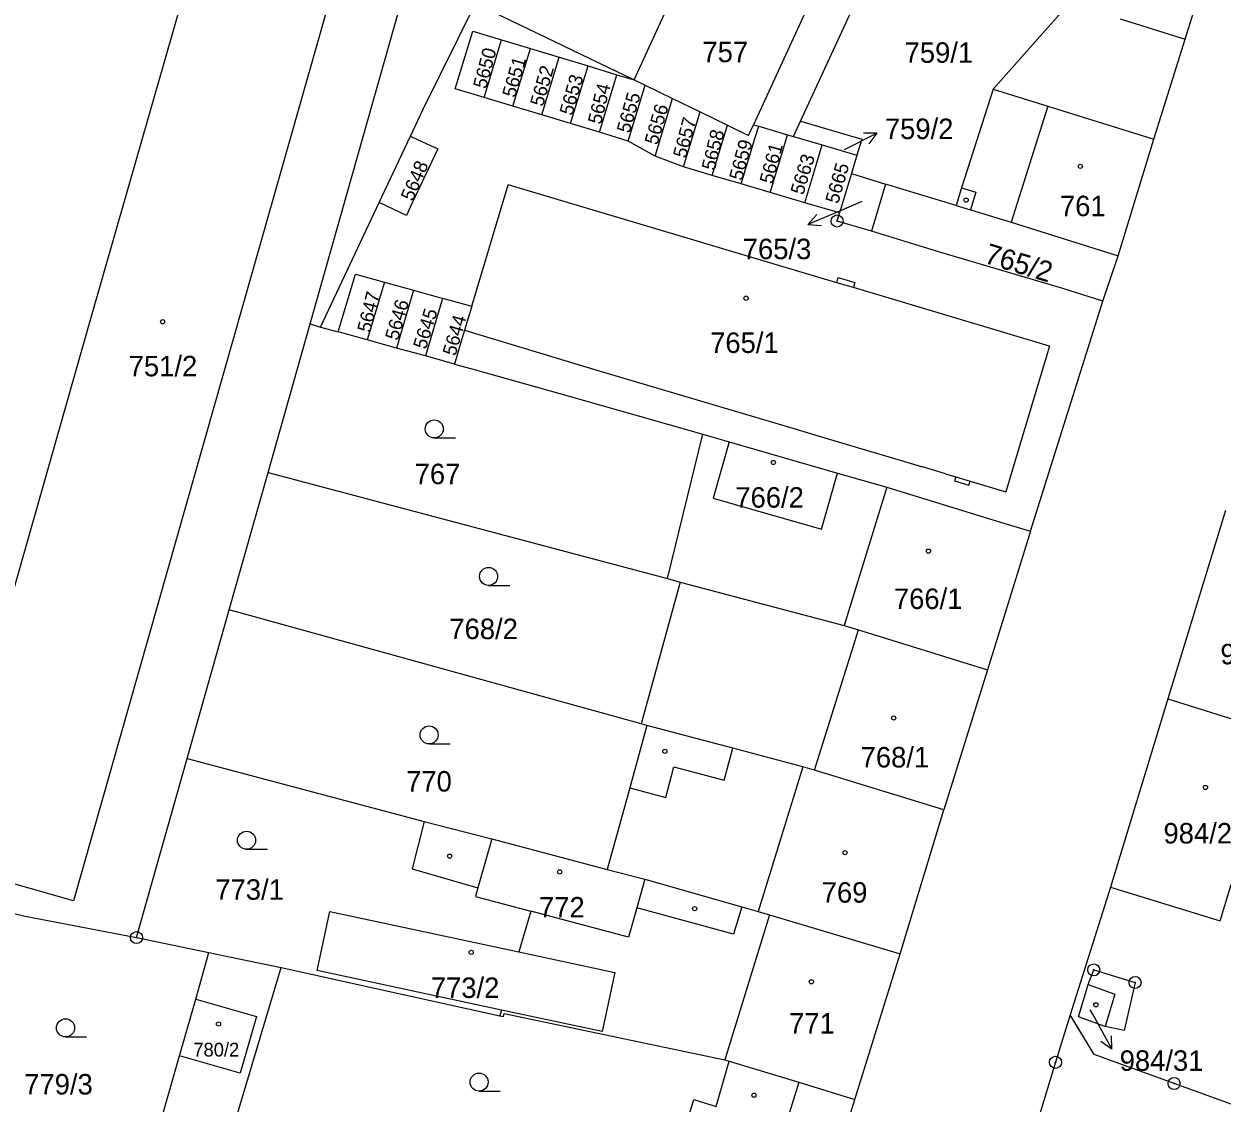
# Model space of a CAD drawing. Extents: x -733394 to -722299, y -1082822 to -1075049.
# Drawn here: x -727904 to -727804.6, y -1079351.3 to -1079261.8 of the extents above; entities that cross this region are included whole.
import ezdxf

# ---------------------------------------------------------------- set-up
doc = ezdxf.new("R2010")
doc.units = 0
for name, color, linetype in [('Hranice parcel', 7, 'Continuous'), ('Parcelní čísla', 7, 'Continuous'), ('Pop  PČ popisy', 7, 'Continuous'), ('Vnitřní kresba', 7, 'Continuous'), ('Značky bodu BP', 7, 'Continuous'), ('Značky budov', 7, 'Continuous'), ('Značky kultur', 7, 'Continuous')]:
    doc.layers.add(name, color=color, linetype=linetype)

msp = doc.modelspace()

# ---------------------------------------------------------------- linework, layer by layer
at = {"layer": 'Hranice parcel'}
for p, q in [((-727853.37, -1079266.43), (-727847.88, -1079254.4)), ((-727866.53, -1079260.08), (-727853.37, -1079266.43)), ((-727817.72, -1079260.59), (-727823.56, -1079267.19)), ((-727865.82, -1079267.89), (-727864.37, -1079263.1)), ((-727864.37, -1079263.1), (-727861.98, -1079263.82)), ((-727863.42, -1079268.61), (-727861.98, -1079263.82)), ((-727861.98, -1079263.82), (-727859.59, -1079264.55)), ((-727861.03, -1079269.34), (-727859.59, -1079264.55)), ((-727859.59, -1079264.55), (-727857.19, -1079265.27)), ((-727858.64, -1079270.06), (-727857.19, -1079265.27)), ((-727857.19, -1079265.27), (-727854.8, -1079266)), ((-727856.25, -1079270.78), (-727854.8, -1079266)), ((-727854.8, -1079266), (-727853.37, -1079266.43)), ((-727853.37, -1079266.43), (-727852.45, -1079266.87)), ((-727853.85, -1079271.51), (-727852.45, -1079266.87)), ((-727852.45, -1079266.87), (-727850.17, -1079267.98)), ((-727863.42, -1079268.61), (-727865.82, -1079267.89)), ((-727851.62, -1079272.75), (-727850.17, -1079267.98)), ((-727850.17, -1079267.98), (-727847.9, -1079269.08)), ((-727861.03, -1079269.34), (-727863.42, -1079268.61)), ((-727858.64, -1079270.06), (-727861.03, -1079269.34)), ((-727849.27, -1079273.64), (-727847.9, -1079269.08)), ((-727847.9, -1079269.08), (-727845.62, -1079270.18)), ((-727856.25, -1079270.78), (-727858.64, -1079270.06)), ((-727846.88, -1079274.35), (-727845.62, -1079270.18)), ((-727843.46, -1079270.15), (-727843.03, -1079270.28)), ((-727843.03, -1079270.28), (-727840.64, -1079270.98)), ((-727840.14, -1079271.13), (-727839.56, -1079269.86)), ((-727874.53, -1079276.61), (-727871.93, -1079271.09)), ((-727853.85, -1079271.51), (-727856.25, -1079270.78)), ((-727851.62, -1079272.75), (-727853.85, -1079271.51)), ((-727840.64, -1079270.98), (-727840.14, -1079271.13)), ((-727840.14, -1079271.13), (-727837.76, -1079271.83)), ((-727813.21, -1079281.03), (-727810.23, -1079271.36)), ((-727837.76, -1079271.83), (-727834.88, -1079272.68)), ((-727849.27, -1079273.64), (-727851.62, -1079272.75)), ((-727834.88, -1079272.68), (-727835.34, -1079274.2)), ((-727846.88, -1079274.35), (-727849.27, -1079273.64)), ((-727844.48, -1079275.06), (-727846.88, -1079274.35)), ((-727835.34, -1079274.2), (-727836.33, -1079277.47)), ((-727835.34, -1079274.2), (-727832.5, -1079275.08)), ((-727842.08, -1079275.77), (-727844.48, -1079275.06)), ((-727832.5, -1079275.08), (-727833.66, -1079278.98)), ((-727826.65, -1079276.85), (-727832.5, -1079275.08)), ((-727839.2, -1079276.62), (-727842.08, -1079275.77)), ((-727879.39, -1079286.94), (-727874.53, -1079276.61)), ((-727836.33, -1079277.47), (-727839.2, -1079276.62)), ((-727814.46, -1079284.79), (-727813.21, -1079281.03)), ((-727874.08, -1079283.22), (-727875.51, -1079288.01)), ((-727874.08, -1079283.22), (-727871.67, -1079283.89)), ((-727871.67, -1079283.89), (-727873.1, -1079288.68)), ((-727820.47, -1079303.88), (-727814.46, -1079284.79)), ((-727883.74, -1079299), (-727880.25, -1079286.67)), ((-727880.25, -1079286.67), (-727879.39, -1079286.94)), ((-727879.39, -1079286.94), (-727877.92, -1079287.35)), ((-727875.51, -1079288.01), (-727877.92, -1079287.35)), ((-727873.1, -1079288.68), (-727875.51, -1079288.01)), ((-727870.69, -1079289.34), (-727873.1, -1079288.68)), ((-727868.28, -1079290.01), (-727870.69, -1079289.34)), ((-727850.61, -1079307.8), (-727847.67, -1079295.84)), ((-727847.67, -1079295.84), (-727845.48, -1079296.47)), ((-727845.48, -1079296.47), (-727836.49, -1079299.06)), ((-727886.96, -1079310.4), (-727883.74, -1079299)), ((-727883.74, -1079299), (-727850.61, -1079307.8)), ((-727804.29, -1079302.16), (-727809.07, -1079317.79)), ((-727820.47, -1079303.88), (-727824.04, -1079315.38)), ((-727849.56, -1079308.1), (-727852.77, -1079319.88)), ((-727850.61, -1079307.8), (-727849.56, -1079308.1)), ((-727849.56, -1079308.1), (-727835.95, -1079311.7)), ((-727890.46, -1079322.76), (-727886.96, -1079310.4)), ((-727852.77, -1079319.88), (-727886.96, -1079310.4)), ((-727824.04, -1079315.38), (-727827.66, -1079327.02)), ((-727809.07, -1079317.79), (-727813.84, -1079333.42)), ((-727809.07, -1079317.79), (-727800.01, -1079320.63)), ((-727852.32, -1079320), (-727852.77, -1079319.88)), ((-727894.66, -1079337.61), (-727890.46, -1079322.76)), ((-727890.46, -1079322.76), (-727870.8, -1079327.98)), ((-727831.29, -1079338.96), (-727827.66, -1079327.02)), ((-727813.84, -1079333.42), (-727817.18, -1079344.01)), ((-727861.95, -1079335.43), (-727862.94, -1079338.8)), ((-727894.66, -1079337.61), (-727888.65, -1079338.84)), ((-727835.04, -1079351.06), (-727831.29, -1079338.96)), ((-727882.65, -1079340.09), (-727864.5, -1079344.11)), ((-727864.36, -1079343.62), (-727864.5, -1079344.11)), ((-727845.48, -1079347.87), (-727839.71, -1079349.61)), ((-727839.71, -1079349.61), (-727835.04, -1079351.06)), ((-727840.81, -1079369.25), (-727835.04, -1079351.06))]:
    msp.add_line(p, q, dxfattribs=at)
for points in [[(-727875.06, -1079247.14), (-727899.89, -1079334.57), (-727911.3, -1079331.32), (-727898.45, -1079286.22), (-727886.35, -1079243.97)], [(-727880.25, -1079286.67), (-727868.91, -1079246.6), (-727874.92, -1079243.71)], [(-727810.23, -1079271.36), (-727807.63, -1079263.04), (-727804.03, -1079251.5), (-727804.69, -1079249.96)], [(-727847.76, -1079254.13), (-727838.1, -1079258.46), (-727843.46, -1079270.15)], [(-727839.56, -1079269.86), (-727834.94, -1079259.88), (-727832.41, -1079254.24)], [(-727871.93, -1079271.09), (-727870.9, -1079268.9), (-727866.53, -1079260.08)], [(-727865.82, -1079267.89), (-727868.21, -1079267.16), (-727866.76, -1079262.38), (-727864.37, -1079263.1)], [(-727823.56, -1079267.19), (-727826.2, -1079275.38), (-727826.65, -1079276.85)], [(-727823.56, -1079267.19), (-727819.05, -1079268.6), (-727810.23, -1079271.36)], [(-727845.62, -1079270.18), (-727843.87, -1079271.03), (-727843.46, -1079270.15)], [(-727844.48, -1079275.06), (-727843.34, -1079271.29), (-727843.03, -1079270.28)], [(-727839.56, -1079269.86), (-727834.48, -1079271.36), (-727834.88, -1079272.68)], [(-727871.93, -1079271.09), (-727871.23, -1079271.42), (-727869.67, -1079272.16), (-727871.95, -1079276.99), (-727872.27, -1079277.68), (-727874.53, -1079276.61)], [(-727842.08, -1079275.77), (-727841.06, -1079272.39), (-727840.64, -1079270.98)], [(-727839.2, -1079276.62), (-727838.21, -1079273.32), (-727837.76, -1079271.83)], [(-727833.66, -1079278.98), (-727836.53, -1079278.14), (-727836.33, -1079277.47)], [(-727826.65, -1079276.85), (-727825.46, -1079277.22), (-727822.08, -1079278.25), (-727813.21, -1079281.03)], [(-727814.46, -1079284.79), (-727817.8, -1079283.75), (-727827.92, -1079280.74), (-727833.66, -1079278.98)], [(-727877.92, -1079287.35), (-727876.49, -1079282.56), (-727874.08, -1079283.22)], [(-727871.67, -1079283.89), (-727869.52, -1079284.48), (-727869.26, -1079284.55)], [(-727869.26, -1079284.55), (-727869.34, -1079284.84), (-727870.69, -1079289.34)], [(-727869.26, -1079284.55), (-727866.84, -1079285.22), (-727867.44, -1079287.21), (-727867.71, -1079288.12), (-727868.28, -1079290.01)], [(-727868.28, -1079290.01), (-727866.54, -1079290.49), (-727858.75, -1079292.68), (-727847.67, -1079295.84)], [(-727845.48, -1079296.47), (-727846.82, -1079301.13), (-727837.83, -1079303.72), (-727836.49, -1079299.06)], [(-727836.49, -1079299.06), (-727832.41, -1079300.24), (-727823.25, -1079303.04), (-727820.47, -1079303.88)], [(-727835.95, -1079311.7), (-727834.76, -1079312.07), (-727824.04, -1079315.38)], [(-727852.32, -1079320), (-727853.72, -1079325.18), (-727855.61, -1079331.95)], [(-727827.66, -1079327.02), (-727838.41, -1079323.72), (-727839.36, -1079323.43), (-727845.18, -1079321.9), (-727852.32, -1079320)], [(-727813.84, -1079333.42), (-727804.74, -1079336.23), (-727803.81, -1079333.2), (-727803.24, -1079333.37), (-727800.29, -1079323.61), (-727800.86, -1079323.44), (-727800.01, -1079320.63)], [(-727870.8, -1079327.98), (-727871.79, -1079331.89), (-727866.33, -1079333.49), (-727866.54, -1079334.21), (-727861.95, -1079335.43)], [(-727870.8, -1079327.98), (-727865.17, -1079329.41), (-727855.61, -1079331.95)], [(-727855.61, -1079331.95), (-727852.48, -1079332.77), (-727844.43, -1079335.06)], [(-727909.33, -1079334.52), (-727903.91, -1079335.82), (-727894.66, -1079337.61)], [(-727844.43, -1079335.06), (-727845.12, -1079337.32), (-727853.15, -1079335.13), (-727853.84, -1079337.58), (-727861.95, -1079335.43)], [(-727844.43, -1079335.06), (-727843.08, -1079335.44), (-727842.12, -1079335.71), (-727831.29, -1079338.96)], [(-727864.36, -1079343.62), (-727879.67, -1079340.34), (-727878.62, -1079335.44), (-727862.94, -1079338.8)], [(-727893.74, -1079356.73), (-727891.09, -1079347.42), (-727889.75, -1079342.71), (-727888.65, -1079338.84)], [(-727888.65, -1079338.84), (-727887.09, -1079339.19), (-727882.65, -1079340.09)], [(-727862.94, -1079338.8), (-727854.98, -1079340.51), (-727856.03, -1079345.41), (-727864.36, -1079343.62)], [(-727888, -1079358.1), (-727887.33, -1079355.76), (-727882.65, -1079340.09)], [(-727814.29, -1079345), (-727816.48, -1079344.19), (-727815.68, -1079341.51), (-727815.23, -1079340.29), (-727811.8, -1079341.33), (-727812.71, -1079345.31), (-727814.29, -1079345)], [(-727864.5, -1079344.11), (-727864.21, -1079344.17), (-727864.14, -1079343.9), (-727845.85, -1079347.76), (-727845.48, -1079347.87)], [(-727817.18, -1079344.01), (-727818.4, -1079347.96), (-727823.14, -1079363.51)], [(-727801.09, -1079352.43), (-727808.56, -1079349.72), (-727815.18, -1079347.32), (-727817.18, -1079344.01)], [(-727839.71, -1079349.61), (-727840.85, -1079353.36), (-727840.22, -1079353.56), (-727842.38, -1079360.57), (-727842.91, -1079360.42), (-727843.53, -1079362.48), (-727851.17, -1079360.13), (-727850.54, -1079358.08), (-727848.42, -1079351.05), (-727846.55, -1079351.62), (-727845.48, -1079347.87)]]:
    msp.add_lwpolyline(points, dxfattribs=at)
at = {"layer": 'Pop  PČ popisy'}
for p, q in [((-727835.9, -1079272.2), (-727833.226, -1079270.838)), ((-727833.226, -1079270.838), (-727834.346, -1079270.846)), ((-727833.226, -1079270.838), (-727833.891, -1079271.738)), ((-727836.18, -1079277.27), (-727838.942, -1079278.443)), ((-727834.47, -1079276.53), (-727836.18, -1079277.27)), ((-727838.942, -1079278.443), (-727838.216, -1079277.59)), ((-727838.942, -1079278.443), (-727837.825, -1079278.512)), ((-727815.54, -1079343.61), (-727815.17, -1079344.25)), ((-727815.17, -1079344.25), (-727813.715, -1079346.875)), ((-727813.715, -1079346.875), (-727813.763, -1079345.756)), ((-727813.715, -1079346.875), (-727814.639, -1079346.242))]:
    msp.add_line(p, q, dxfattribs=at)
at = {"layer": 'Vnitřní kresba'}
for p, q in [((-727813.02, -1079261.36), (-727807.63, -1079263.04)), ((-727819.05, -1079268.6), (-727822.08, -1079278.25)), ((-727866.84, -1079285.22), (-727863.83, -1079275.13)), ((-727852.86, -1079278.39), (-727863.83, -1079275.13)), ((-727826.2, -1079275.38), (-727825.01, -1079275.74)), ((-727825.01, -1079275.74), (-727825.46, -1079277.22)), ((-727836.55, -1079283.26), (-727852.86, -1079278.39)), ((-727836.55, -1079283.26), (-727836.43, -1079282.82)), ((-727835.17, -1079283.67), (-727836.55, -1079283.26)), ((-727836.43, -1079282.82), (-727835.04, -1079283.24)), ((-727835.04, -1079283.24), (-727835.17, -1079283.67)), ((-727818.91, -1079288.52), (-727835.17, -1079283.67)), ((-727867.44, -1079287.21), (-727856.47, -1079290.51)), ((-727818.91, -1079288.52), (-727820.78, -1079294.78)), ((-727856.47, -1079290.51), (-727840.21, -1079295.34)), ((-727840.21, -1079295.34), (-727838.3, -1079295.91)), ((-727820.78, -1079294.78), (-727822.52, -1079300.62)), ((-727838.3, -1079295.91), (-727829.45, -1079298.55)), ((-727827.54, -1079299.12), (-727829.45, -1079298.55)), ((-727827.54, -1079299.12), (-727826.68, -1079299.38)), ((-727832.41, -1079300.24), (-727835.95, -1079311.7)), ((-727826.68, -1079299.38), (-727826.78, -1079299.71)), ((-727826.78, -1079299.71), (-727825.58, -1079300.06)), ((-727826.68, -1079299.38), (-727825.48, -1079299.73)), ((-727825.58, -1079300.06), (-727825.48, -1079299.73)), ((-727825.48, -1079299.73), (-727822.52, -1079300.62)), ((-727838.41, -1079323.72), (-727834.76, -1079312.07)), ((-727845.89, -1079324.55), (-727845.18, -1079321.9)), ((-727850.74, -1079325.98), (-727850.06, -1079323.44)), ((-727850.06, -1079323.44), (-727845.89, -1079324.55)), ((-727839.36, -1079323.43), (-727843.08, -1079335.44)), ((-727853.72, -1079325.18), (-727850.74, -1079325.98)), ((-727865.17, -1079329.41), (-727866.33, -1079333.49)), ((-727852.48, -1079332.77), (-727853.15, -1079335.13)), ((-727842.12, -1079335.71), (-727845.85, -1079347.76)), ((-727889.75, -1079342.71), (-727884.71, -1079344.16)), ((-727884.71, -1079344.16), (-727886.05, -1079348.85)), ((-727886.05, -1079348.85), (-727891.09, -1079347.42))]:
    msp.add_line(p, q, dxfattribs=at)
msp.add_lwpolyline([(-727815.68, -1079341.51), (-727813.49, -1079342.31), (-727814.29, -1079345)], dxfattribs=at)
at = {"layer": 'Značky bodu BP'}
for centre, radius in [((-727836.53, -1079278.14), 0.5), ((-727836.53, -1079278.14), 0.0303), ((-727894.66, -1079337.61), 0.5), ((-727894.66, -1079337.61), 0.0303), ((-727815.23, -1079340.29), 0.5), ((-727815.23, -1079340.29), 0.0303), ((-727811.8, -1079341.33), 0.5), ((-727811.8, -1079341.33), 0.0303), ((-727818.4, -1079347.96), 0.5), ((-727818.4, -1079347.96), 0.0303), ((-727808.56, -1079349.72), 0.5), ((-727808.56, -1079349.72), 0.0303)]:
    msp.add_circle(centre, radius, dxfattribs=at)
at = {"layer": 'Značky budov'}
for centre in [(-727816.337, -1079273.599), (-727825.817, -1079276.409), (-727844.077, -1079284.549), (-727892.487, -1079286.499), (-727841.817, -1079298.179), (-727828.947, -1079305.539), (-727831.827, -1079319.389), (-727850.817, -1079322.149), (-727805.957, -1079325.149), (-727868.677, -1079330.849), (-727835.867, -1079330.559), (-727859.547, -1079332.159), (-727848.347, -1079335.209), (-727866.887, -1079338.829), (-727838.657, -1079341.279), (-727815.047, -1079343.189), (-727887.857, -1079344.779), (-727843.417, -1079350.689)]:
    msp.add_circle(centre, 0.175, dxfattribs=at)
at = {"layer": 'Značky kultur'}
for p, q in [((-727869.953, -1079296.14), (-727868.203, -1079296.14)), ((-727865.443, -1079308.39), (-727863.693, -1079308.39)), ((-727870.383, -1079321.54), (-727868.633, -1079321.54)), ((-727885.533, -1079330.28), (-727883.783, -1079330.28)), ((-727900.553, -1079345.85), (-727898.803, -1079345.85)), ((-727866.233, -1079350.35), (-727864.483, -1079350.35))]:
    msp.add_line(p, q, dxfattribs=at)
for centre in [(-727869.953, -1079295.39), (-727865.443, -1079307.64), (-727870.383, -1079320.79), (-727885.533, -1079329.53), (-727900.553, -1079345.1), (-727866.233, -1079349.6)]:
    msp.add_circle(centre, 0.75, dxfattribs=at)

# ---------------------------------------------------------------- texts
at = {"layer": 'Parcelní čísla'}
for s, height, p in [('757', 1.7, (-727847.7, -1079264.96)), ('759/1', 1.7, (-727830.923, -1079265.01)), ('759/2', 1.7, (-727832.56, -1079271.34)), ('761', 1.7, (-727818.03, -1079277.74)), ('765/3', 1.7, (-727844.353, -1079281.31)), ('765/1', 1.7, (-727847.06, -1079289.09)), ('751/2', 1.7, (-727895.31, -1079291.03)), ('767', 1.7, (-727871.58, -1079299.98)), ('766/2', 1.7, (-727844.97, -1079301.93)), ('766/1', 1.7, (-727831.81, -1079310.34)), ('768/2', 1.7, (-727868.7, -1079312.84)), ('984/1', 1.7, (-727804.72, -1079314.93)), ('768/1', 1.7, (-727834.57, -1079323.49)), ('770', 1.7, (-727872.29, -1079325.49)), ('984/2', 1.7, (-727809.44, -1079329.8)), ('773/1', 1.7, (-727888.12, -1079334.47)), ('769', 1.7, (-727837.8, -1079334.71)), ('772', 1.7, (-727861.26, -1079335.94)), ('773/2', 1.7, (-727870.24, -1079342.62)), ('771', 1.7, (-727840.51, -1079345.58)), ('780/2', 1.139, (-727889.948, -1079347.479)), ('984/31', 1.7, (-727813.075, -1079348.67)), ('779/3', 1.7, (-727903.98, -1079350.63))]:
    msp.add_text(s, height=height, dxfattribs=at).set_placement(p)
for s, height, rotation, p in [('5650', 1.139, 75, (-727865.654, -1079267.229)), ('5651', 1.139, 74, (-727863.245, -1079267.961)), ('5652', 1.139, 74, (-727860.935, -1079268.701)), ('5653', 1.139, 74, (-727858.495, -1079269.441)), ('5654', 1.139, 76, (-727856.123, -1079270.177)), ('5655', 1.139, 74, (-727853.745, -1079270.921)), ('5656', 1.139, 74, (-727851.435, -1079271.891)), ('5657', 1.139, 75, (-727849.064, -1079272.989)), ('5658', 1.139, 76, (-727846.683, -1079274.007)), ('5659', 1.139, 75, (-727844.404, -1079274.839)), ('5661', 1.139, 75, (-727841.884, -1079275.129)), ('5648', 1.139, 67, (-727871.732, -1079276.568)), ('5663', 1.139, 73, (-727839.336, -1079276.042)), ('5665', 1.139, 74, (-727836.435, -1079276.771)), ('765/2', 1.7, 343, (-727824.408, -1079281.592)), ('5647', 1.139, 76, (-727875.263, -1079287.457)), ('5646', 1.139, 74, (-727872.965, -1079288.111)), ('5645', 1.139, 73, (-727870.646, -1079288.852)), ('5644', 1.139, 74, (-727868.195, -1079289.401))]:
    msp.add_text(s, height=height, rotation=rotation, dxfattribs=at).set_placement(p)

doc.saveas('drawing.dxf')
